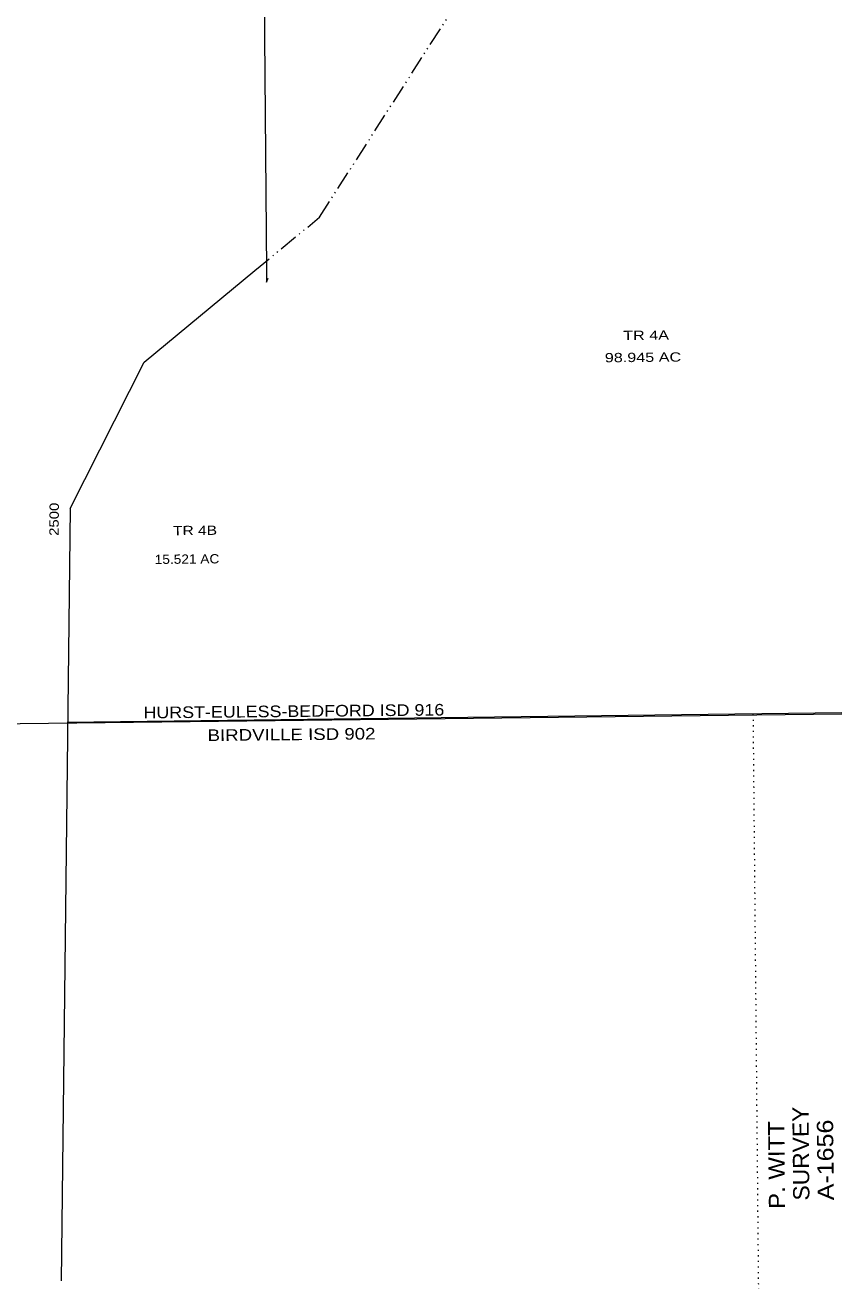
# Model space of a CAD drawing. Extents: x 2356373 to 2371954, y 6966197 to 6989612.
# Drawn here: x 2364566 to 2365972, y 6974303 to 6976463 of the extents above; entities that cross this region are included whole.
import ezdxf

# ---------------------------------------------------------------- set-up
doc = ezdxf.new("R2010")
doc.units = 0
doc.header["$LTSCALE"] = 6.4
doc.linetypes.add('DASH_DOUBLE_DOT', pattern=[9.2, 5, -1.2, 0.3, -1.2, 0.3, -1.2])
doc.linetypes.add('DOTTED', pattern=[1.5, 0.3, -1.2])
for name, color, linetype in [('10', 7, 'Continuous'), ('11', 7, 'Continuous'), ('20', 7, 'Continuous'), ('21', 7, 'Continuous'), ('24', 7, 'Continuous')]:
    doc.layers.add(name, color=color, linetype=linetype)
for name, color, linetype, lineweight in [('13', 7, 'Continuous', 13), ('15', 7, 'Continuous', 13), ('23', 7, 'Continuous', 13), ('4', 7, 'Continuous', 13)]:
    doc.layers.add(name, color=color, linetype=linetype, lineweight=lineweight)

msp = doc.modelspace()

# ---------------------------------------------------------------- linework, layer by layer
at = {"layer": '13'}
msp.add_line((2364974.72, 6976837.403), (2364981.542, 6976041.082), dxfattribs=at)
msp.add_lwpolyline([(2364981.542, 6976041.082), (2364981.737, 6976021.091), (2364984.672, 6976027.817)], dxfattribs=at)
at = {"layer": '15', "linetype": 'DASH_DOUBLE_DOT'}
for p, q in [((2365072.838, 6976132.575), (2365295.893, 6976480.185)), ((2364961.88, 6976040.866), (2365072.838, 6976132.575))]:
    msp.add_line(p, q, dxfattribs=at)
at = {"layer": '15'}
for p, q in [((2364771.426, 6975883.45), (2364961.88, 6976040.866)), ((2364643.725, 6975631.453), (2364771.426, 6975883.45)), ((2364643.725, 6975631.453), (2364628.393, 6974302.602))]:
    msp.add_line(p, q, dxfattribs=at)
at = {"layer": '23'}
msp.add_lwpolyline([(2365971.781, 6975277.415), (2364411.374, 6975259.389), (2364396.568, 6976868.515)], dxfattribs=at)
at = {"layer": '4'}
msp.add_line((2365971.758, 6975279.715), (2364638.678, 6975263.141), dxfattribs=at)
at = {"layer": '4', "linetype": 'DOTTED'}
msp.add_line((2365818.818, 6975277.812), (2365841.332, 6972883.773), dxfattribs=at)

# ---------------------------------------------------------------- texts
at = {"layer": '10'}
for s, width, p in [('TR 4A', 1.3, (2365595.556, 6975921.247)), ('TR 4B', 1.25, (2364821.06, 6975585.527))]:
    msp.add_text(s, height=15.99, rotation=0.563, dxfattribs=dict(at, width=width)).set_placement(p)
at = {"layer": '11'}
for s, width, p in [('98.945 AC', 1.3, (2365563.938, 6975883.048)), ('15.521 AC', 1.1, (2364789.554, 6975536.031))]:
    msp.add_text(s, height=15.99, rotation=0.563, dxfattribs=dict(at, width=width)).set_placement(p)
at = {"layer": '20'}
for s, width, p in [('SURVEY', 1.05, (2365916.012, 6974440.991)), ('P. WITT', 1.1, (2365874.165, 6974426.583)), ('A-1656', 1.15, (2365957.998, 6974441.404))]:
    msp.add_text(s, height=27.99, rotation=90.563, dxfattribs=dict(at, width=width)).set_placement(p)
at = {"layer": '21'}
for s, width, p in [('HURST-EULESS-BEDFORD ISD 916', 1.15, (2364770.171, 6975270.311)), ('BIRDVILLE ISD 902', 1.2, (2364880.524, 6975231.406))]:
    msp.add_text(s, height=19.99, rotation=0.563, dxfattribs=dict(at, width=width)).set_placement(p)
at = {"layer": '24', "width": 1.2}
msp.add_text('2500', height=15.99, rotation=89.55, dxfattribs=at).set_placement((2364624.123, 6975584.393))

doc.saveas('drawing.dxf')
